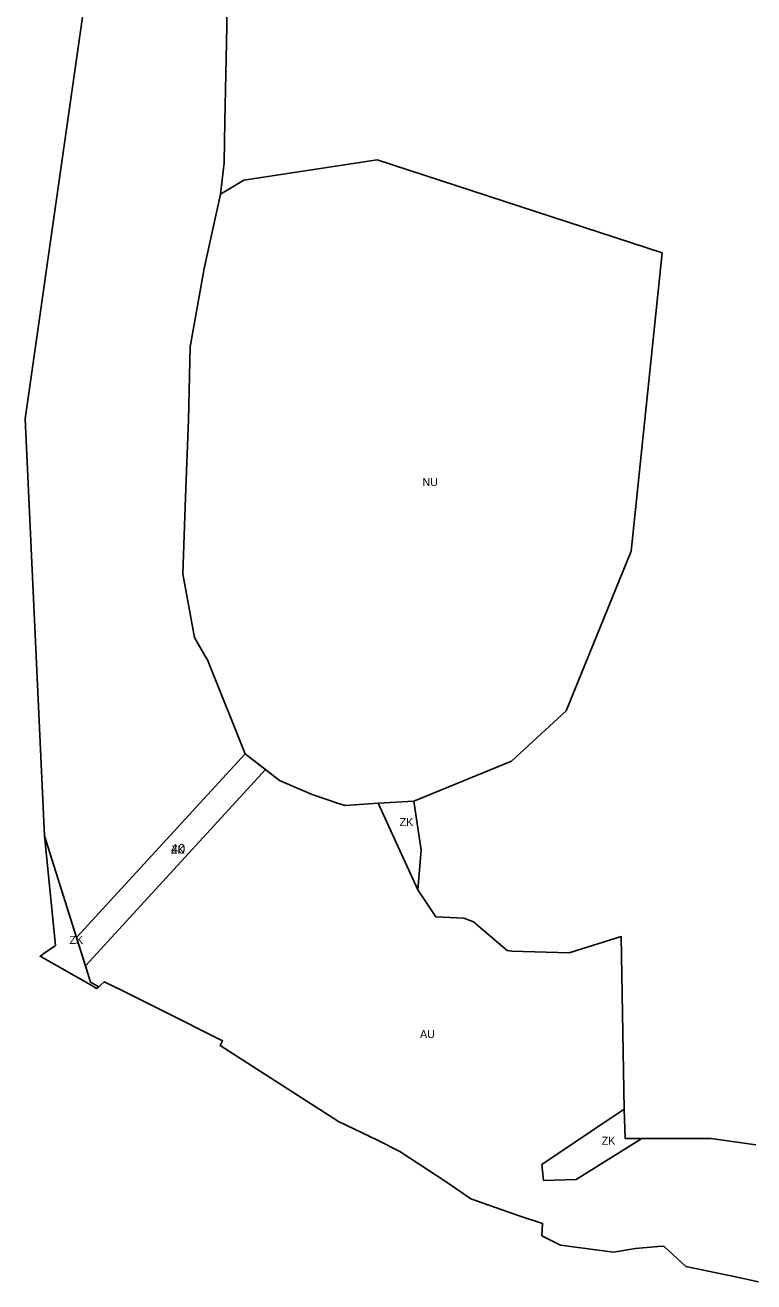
# Model space of a CAD drawing. Extents: x -521261 to -517465, y -1182764 to -1179456.
# Drawn here: x -521261 to -520806, y -1181658 to -1180873 of the extents above; entities that cross this region are included whole.
import ezdxf

# ---------------------------------------------------------------- set-up
doc = ezdxf.new("R2010")
doc.units = 0
for name, color, linetype in [('90710013', 7, 'Continuous'), ('90710023', 7, 'Continuous'), ('90730013', 7, 'Continuous'), ('90750013', 7, 'Continuous'), ('90770013', 7, 'Continuous'), ('ID_navrh', 7, 'Continuous')]:
    doc.layers.add(name, color=color, linetype=linetype)

msp = doc.modelspace()

# ---------------------------------------------------------------- linework, layer by layer
at = {"layer": '90710013'}
for points in [[(-521013.8, -1181388.33), (-521015.94, -1181413.17), (-521040.75, -1181359.05), (-521018.46, -1181357.74)], [(-521250.74, -1181453.83), (-521249.55, -1181452.99), (-521242.23, -1181447.88), (-521249.27, -1181379.35), (-521221.03, -1181468.82), (-521220.37, -1181470.88), (-521215.29, -1181473.73), (-521216.62, -1181474.75), (-521220.04, -1181472.8), (-521251.97, -1181454.65)], [(-520907.255, -1181563.785), (-520887.02, -1181550.13), (-520886.32, -1181568.63), (-520875.964, -1181568.617), (-520917.031, -1181594.116), (-520937.51, -1181594.75), (-520938.5, -1181584.87)]]:
    msp.add_lwpolyline(points, close=True, dxfattribs=at)
at = {"layer": '90710023'}
msp.add_lwpolyline([(-521123.91, -1181328.24), (-521111.193, -1181338.047), (-521223.634, -1181460.569), (-521229.192, -1181442.961)], close=True, dxfattribs=at)
at = {"layer": '90730013'}
msp.add_lwpolyline([(-520957.49, -1181332.89), (-521018.46, -1181357.74), (-521040.75, -1181359.05), (-521061.3, -1181360.4), (-521066.19, -1181358.96), (-521082.04, -1181353.53), (-521102.32, -1181344.89), (-521123.91, -1181328.24), (-521147.36, -1181269.44), (-521148.84, -1181267.14), (-521155.45, -1181255.63), (-521162.81, -1181215.7), (-521161.12, -1181167.95), (-521159.23, -1181119.6), (-521158.27, -1181073.9), (-521149.47, -1181024.96), (-521139.18, -1180978.59), (-521124.61, -1180969.86), (-521041.32, -1180957.03), (-520863.295, -1181015.242), (-520882.71, -1181201.62), (-520923.27, -1181301.34)], close=True, dxfattribs=at)
at = {"layer": '90750013'}
for points in [[(-521134.59, -1180840.77), (-521135.49, -1180884), (-521136.51, -1180932.9), (-521137.03, -1180959.08), (-521139.18, -1180978.59), (-521149.47, -1181024.96), (-521158.27, -1181073.9), (-521159.23, -1181119.6), (-521161.12, -1181167.95), (-521162.81, -1181215.7), (-521155.45, -1181255.63), (-521148.84, -1181267.14), (-521147.36, -1181269.44), (-521123.91, -1181328.24), (-521229.192, -1181442.961), (-521249.27, -1181379.35), (-521261.28, -1181118.92), (-521236.44, -1180945.21), (-521211.68, -1180771.41)], [(-520803.11, -1181658.11), (-520817.41, -1181654.92), (-520848.48, -1181648.48), (-520862.22, -1181635.85), (-520865.97, -1181636.11), (-520879.87, -1181637.27), (-520893.72, -1181639.51), (-520926.89, -1181635.27), (-520938.46, -1181629.35), (-520938.04, -1181621.68), (-520952.58, -1181616.94), (-520982.79, -1181606.31), (-520998.32, -1181595.58), (-521027.28, -1181576.76), (-521041.22, -1181569.52), (-521065.57, -1181557.94), (-521139.48, -1181510.44), (-521137.91, -1181507.51), (-521175.72, -1181488.6), (-521200.31, -1181476.36), (-521211.86, -1181470.62), (-521214.11, -1181472.65), (-521215.29, -1181473.73), (-521220.37, -1181470.88), (-521221.03, -1181468.82), (-521223.634, -1181460.569), (-521111.193, -1181338.047), (-521102.32, -1181344.89), (-521082.04, -1181353.53), (-521066.19, -1181358.96), (-521061.3, -1181360.4), (-521040.75, -1181359.05), (-521015.94, -1181413.17), (-521004.72, -1181430.1), (-520987.18, -1181430.86), (-520981.07, -1181433.26), (-520960.07, -1181451.01), (-520957.12, -1181451.45), (-520921.32, -1181452.64), (-520888.84, -1181442.39), (-520887.02, -1181550.13), (-520907.255, -1181563.785), (-520938.5, -1181584.87), (-520937.51, -1181594.75), (-520917.031, -1181594.116), (-520875.964, -1181568.617), (-520832.67, -1181568.56), (-520804.67, -1181572.45)]]:
    msp.add_lwpolyline(points, dxfattribs=at)
at = {"layer": '90770013'}
msp.add_lwpolyline([(-520804.67, -1181572.45), (-520832.67, -1181568.56), (-520886.32, -1181568.63), (-520887.02, -1181550.13), (-520888.84, -1181442.39), (-520921.32, -1181452.64), (-520957.12, -1181451.45), (-520960.07, -1181451.01), (-520981.07, -1181433.26), (-520987.18, -1181430.86), (-521004.72, -1181430.1), (-521015.94, -1181413.17), (-521013.8, -1181388.33), (-521018.46, -1181357.74), (-520957.49, -1181332.89), (-520923.27, -1181301.34), (-520882.71, -1181201.62), (-520863.295, -1181015.242), (-521041.32, -1180957.03), (-521124.61, -1180969.86), (-521139.18, -1180978.59), (-521137.03, -1180959.08), (-521136.51, -1180932.9), (-521135.49, -1180884), (-521134.59, -1180840.77)], dxfattribs=at)

# ---------------------------------------------------------------- texts
at = {"layer": '90710013'}
for rotation, p in [(0, (-521027.275, -1181373.351)), (360, (-521233.63, -1181446.988)), (0, (-520901.101, -1181572.44))]:
    msp.add_text('ZK', height=5, rotation=rotation, dxfattribs=at).set_placement(p)
at = {"layer": '90710023'}
msp.add_text('ZK', height=5, rotation=0, dxfattribs=at).set_placement((-521170.193, -1181390.504))
at = {"layer": '90730013'}
msp.add_text('NU', height=5, rotation=360, dxfattribs=at).set_placement((-521013.052, -1181160.905))
at = {"layer": '90750013'}
msp.add_text('AU', height=5, rotation=0, dxfattribs=at).set_placement((-521014.554, -1181505.796))
at = {"layer": 'ID_navrh'}
msp.add_text('40', height=6, rotation=360, dxfattribs=at).set_placement((-521170.193, -1181390.504))

doc.saveas('drawing.dxf')
